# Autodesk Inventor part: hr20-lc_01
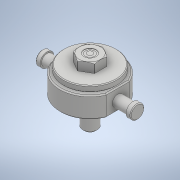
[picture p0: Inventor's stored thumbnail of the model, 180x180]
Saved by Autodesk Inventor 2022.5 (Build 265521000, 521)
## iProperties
Part Number: hr20-lc_01
Material: 一般
Document SubType Name: Modeling
Designer: ImaoCorp
Density: 1 g/cm^3
Appearance: 既定
Author: ImaoCorp
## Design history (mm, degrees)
feature "hr20-lc_01"
node "ソリッド1"
